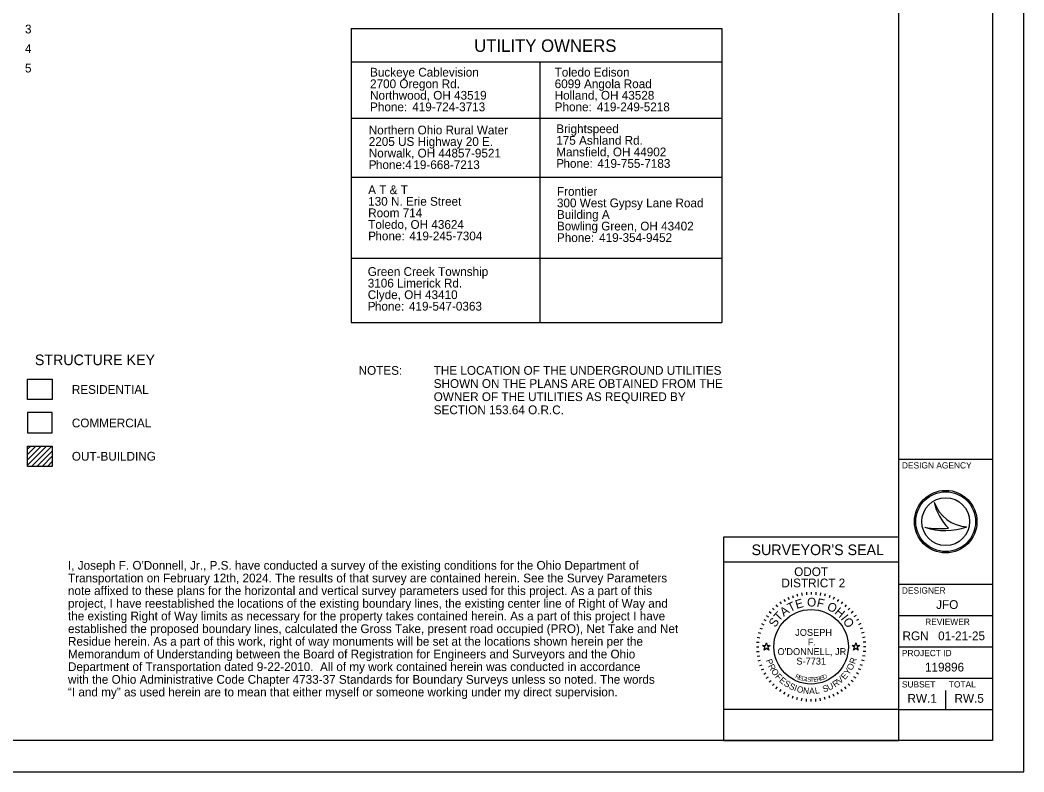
# Model space of a CAD drawing. Extents: x 0 to 34, y 0 to 22.
# Drawn here: x 17.96 to 34, y 0 to 12.02 of the extents above; entities that cross this region are included whole.
import ezdxf

# ---------------------------------------------------------------- set-up
doc = ezdxf.new("R2010")
doc.units = 0
for name, color, linetype in [('Default', 7, 'Continuous'), ('SC_Shading1', 7, 'Continuous'), ('SH_Border', 7, 'Continuous'), ('SH_Cut_Line', 7, 'Continuous'), ('SH_Data', 7, 'Continuous'), ('SH_Text', 7, 'Continuous')]:
    doc.layers.add(name, color=color, linetype=linetype)

msp = doc.modelspace()

# ---------------------------------------------------------------- linework, layer by layer
at = {"layer": 'Default'}
for points in [[(29.824, 2.02), (29.871, 2.02), (29.885, 2.065), (29.899, 2.02), (29.946, 2.02), (29.908, 1.992), (29.923, 1.948), (29.885, 1.975), (29.847, 1.948), (29.862, 1.992)], [(31.254, 2.02), (31.301, 2.02), (31.315, 2.065), (31.329, 2.02), (31.376, 2.02), (31.338, 1.992), (31.353, 1.948), (31.315, 1.975), (31.277, 1.948), (31.292, 1.992)]]:
    msp.add_lwpolyline(points, close=True, dxfattribs=at)
at = {"layer": 'SC_Shading1'}
msp.add_lwpolyline([(18.078, 5.417), (18.475, 5.417), (18.475, 5.743), (18.078, 5.743)], close=True, dxfattribs=at)
at = {"layer": 'SH_Border'}
for p, q in [((32, 0.5), (32, 21.5)), ((32, 5), (33.5, 5)), ((32, 3), (33.5, 3)), ((32, 2.5), (33.5, 2.5)), ((32, 2), (33.5, 2)), ((32, 1.5), (33.5, 1.5)), ((32, 1), (33.5, 1))]:
    msp.add_line(p, q, dxfattribs=at)
msp.add_lwpolyline([(1.5, 21.5), (33.5, 21.5), (33.5, 0.5), (1.5, 0.5)], close=True, dxfattribs=at)
at = {"layer": 'SH_Cut_Line'}
msp.add_lwpolyline([(0, 0), (34, 0), (34, 22), (0, 22)], close=True, dxfattribs=at)
at = {"layer": 'SH_Data'}
for p, q in [((32.567, 4.31), (32.567, 4.31)), ((32.417, 3.91), (32.417, 3.91)), ((32.75, 4), (32.75, 4)), ((33.087, 3.919), (33.087, 3.919)), ((32, 3.75), (29.2, 3.75)), ((29.2, 3.75), (29.2, 0.5)), ((32, 0.5), (32, 3.75)), ((32, 3.35), (29.2, 3.35)), ((30.163, 2.758), (30.183, 2.723)), ((30.23, 2.793), (30.247, 2.757)), ((30.301, 2.822), (30.314, 2.785)), ((30.374, 2.845), (30.384, 2.807)), ((30.448, 2.862), (30.455, 2.822)), ((30.524, 2.872), (30.527, 2.832)), ((30.6, 2.875), (30.6, 2.835)), ((30.676, 2.872), (30.673, 2.832)), ((30.752, 2.862), (30.745, 2.822)), ((30.826, 2.845), (30.816, 2.807)), ((30.899, 2.822), (30.886, 2.785)), ((30.97, 2.793), (30.953, 2.757)), ((31.037, 2.758), (31.017, 2.723)), ((29.981, 2.619), (30.01, 2.59)), ((30.038, 2.67), (30.063, 2.64)), ((30.098, 2.717), (30.121, 2.684)), ((31.102, 2.717), (31.079, 2.684)), ((31.162, 2.67), (31.137, 2.64)), ((31.219, 2.619), (31.19, 2.59)), ((29.842, 2.438), (29.877, 2.418)), ((29.883, 2.502), (29.916, 2.479)), ((29.93, 2.562), (29.96, 2.537)), ((31.27, 2.562), (31.24, 2.537)), ((31.317, 2.502), (31.284, 2.479)), ((31.358, 2.438), (31.323, 2.418)), ((29.778, 2.299), (29.815, 2.286)), ((29.807, 2.37), (29.843, 2.353)), ((31.393, 2.37), (31.357, 2.353)), ((31.422, 2.299), (31.385, 2.286)), ((29.738, 2.152), (29.778, 2.145)), ((29.755, 2.226), (29.793, 2.216)), ((31.445, 2.226), (31.407, 2.216)), ((31.462, 2.152), (31.422, 2.145)), ((29.725, 2), (29.765, 2)), ((29.728, 2.076), (29.768, 2.073)), ((29.728, 1.924), (29.768, 1.927)), ((31.472, 2.076), (31.432, 2.073)), ((31.472, 1.924), (31.432, 1.927)), ((31.475, 2), (31.435, 2)), ((29.738, 1.848), (29.778, 1.855)), ((29.755, 1.774), (29.793, 1.784)), ((31.445, 1.774), (31.407, 1.784)), ((31.462, 1.848), (31.422, 1.855)), ((29.778, 1.701), (29.815, 1.714)), ((29.807, 1.63), (29.843, 1.647)), ((31.393, 1.63), (31.357, 1.647)), ((31.422, 1.701), (31.385, 1.714)), ((29.842, 1.563), (29.877, 1.583)), ((29.883, 1.498), (29.916, 1.521)), ((29.93, 1.438), (29.96, 1.463)), ((31.27, 1.438), (31.24, 1.463)), ((31.317, 1.498), (31.284, 1.521)), ((31.358, 1.563), (31.323, 1.583)), ((29.981, 1.381), (30.01, 1.41)), ((30.038, 1.33), (30.063, 1.36)), ((30.098, 1.283), (30.121, 1.316)), ((31.102, 1.283), (31.079, 1.316)), ((31.162, 1.33), (31.137, 1.36)), ((31.219, 1.381), (31.19, 1.41)), ((32.75, 1), (32.75, 1.3)), ((30.163, 1.242), (30.183, 1.277)), ((30.23, 1.207), (30.247, 1.243)), ((30.301, 1.178), (30.314, 1.215)), ((30.374, 1.155), (30.384, 1.193)), ((30.448, 1.138), (30.455, 1.178)), ((30.524, 1.128), (30.527, 1.168)), ((30.6, 1.125), (30.6, 1.165)), ((30.676, 1.128), (30.673, 1.168)), ((30.752, 1.138), (30.745, 1.178)), ((30.826, 1.155), (30.816, 1.193)), ((30.899, 1.178), (30.886, 1.215)), ((30.97, 1.207), (30.953, 1.243)), ((31.037, 1.242), (31.017, 1.277)), ((32, 0.5), (29.2, 0.5))]:
    msp.add_line(p, q, dxfattribs=at)
msp.add_lwpolyline([(32, 0.5), (32, 1), (29.2, 1), (29.2, 0.5)], close=True, dxfattribs=at)
for centre, radius in [((32.75, 4), 0.5), ((32.75, 4), 0.477), ((32.75, 4), 0.477), ((32.75, 4), 0.382), ((30.6, 2), 0.595)]:
    msp.add_circle(centre, radius, dxfattribs=at)
for centre, radius, start, end in [((33.116, 4.498), 0.58, 198.9257, 198.9319), ((33.347, 4.47), 0.796, 191.6379, 191.6421), ((33.116, 4.498), 0.58, 198.9319, 267.1657), ((33.347, 4.47), 0.796, 191.6421, 226.0947), ((32.739, 4.87), 1.013, 251.4576, 290.0832), ((32.648, 5.154), 1.266, 259.4964, 259.4995), ((32.739, 4.87), 1.013, 251.4527, 251.4576), ((32.648, 5.154), 1.266, 259.4995, 276.6672)]:
    msp.add_arc(centre, radius, start, end, dxfattribs=at)
at = {"layer": 'SH_Text'}
for p, q in [((23.251, 11.882), (29.172, 11.882)), ((23.251, 11.882), (23.251, 7.184)), ((29.172, 11.882), (29.172, 7.184)), ((23.251, 11.351), (29.172, 11.351)), ((26.267, 11.351), (26.267, 7.184)), ((23.251, 10.449), (29.172, 10.449)), ((23.251, 9.505), (29.172, 9.505)), ((23.251, 8.212), (29.172, 8.212)), ((23.251, 7.184), (29.172, 7.184)), ((18.078, 5.206), (18.079, 5.207)), ((18.078, 5.156), (18.129, 5.207)), ((18.078, 5.071), (18.214, 5.207)), ((18.078, 4.986), (18.299, 5.207)), ((18.078, 4.902), (18.383, 5.207)), ((18.142, 4.881), (18.468, 5.207)), ((18.227, 4.881), (18.475, 5.129)), ((18.312, 4.881), (18.475, 5.045)), ((18.078, 4.886), (18.082, 4.881)), ((18.396, 4.881), (18.475, 4.96))]:
    msp.add_line(p, q, dxfattribs=at)
for points in [[(18.078, 6.278), (18.475, 6.278), (18.475, 5.952), (18.078, 5.952)], [(18.078, 5.207), (18.475, 5.207), (18.475, 4.881), (18.078, 4.881)]]:
    msp.add_lwpolyline(points, close=True, dxfattribs=at)

# ---------------------------------------------------------------- texts
at = {"layer": 'SH_Data'}
for s, height, p in [('3', 0.14, (18.038, 11.803)), ('4', 0.14, (18.038, 11.491)), ('5', 0.14, (18.038, 11.179)), ('DESIGN AGENCY', 0.1, (32.05, 4.85)), ("SURVEYOR'S SEAL", 0.17, (29.648, 3.465)), ('ODOT', 0.14, (30.329, 3.13)), ('DISTRICT 2', 0.14, (30.125, 2.95)), ('DESIGNER', 0.1, (32.05, 2.85)), ('JFO', 0.14, (32.598, 2.605)), ('REVIEWER', 0.1, (32.422, 2.35)), ('JOSEPH', 0.11, (30.345, 2.175)), ('RGN', 0.14, (32.06, 2.105)), ('01-21-25', 0.14, (32.629, 2.105)), ('F.', 0.11, (30.546, 2.022)), ("O'DONNELL, JR.", 0.11, (30.062, 1.868)), ('PROJECT ID', 0.1, (32.05, 1.85)), ('S-7731', 0.11, (30.364, 1.715)), ('119896', 0.14, (32.419, 1.605)), ('SUBSET', 0.1, (32.05, 1.35)), ('TOTAL', 0.1, (32.8, 1.35)), ('RW.1', 0.14, (32.14, 1.105)), ('RW.5', 0.14, (32.891, 1.105))]:
    msp.add_text(s, height=height, dxfattribs=at).set_placement(p)
for s, height, rotation, p in [('E', 0.14, 15.7571, (30.368, 2.604)), ('O', 0.14, 359.7812, (30.535, 2.644)), ('F', 0.14, 347.4362, (30.681, 2.642)), ('T', 0.14, 46.4344, (30.088, 2.396)), ('A', 0.14, 36.4747, (30.163, 2.478)), ('T', 0.14, 25.7167, (30.262, 2.552)), ('O', 0.14, 332.2586, (30.84, 2.602)), ('H', 0.14, 319.9136, (30.963, 2.536)), ('S', 0.14, 57.1924, (30.028, 2.301)), ('I', 0.14, 308.367, (31.066, 2.448)), ('O', 0.14, 303.1491, (31.102, 2.409)), ('P', 0.1, 289.7431, (29.875, 1.784)), ('R', 0.1, 70.983, (31.301, 1.717)), ('R', 0.1, 296.9802, (29.909, 1.693)), ('O', 0.1, 304.7158, (29.953, 1.608)), ('Y', 0.1, 55.5058, (31.2, 1.54)), ('O', 0.1, 62.7428, (31.25, 1.613)), ('F', 0.1, 312.956, (30.019, 1.516)), ('E', 0.1, 319.6885, (30.081, 1.45)), ('S', 0.1, 326.9255, (30.155, 1.389)), ('R', 0.07, 334.487, (30.337, 1.505)), ('E', 0.07, 341.04, (30.391, 1.48)), ('G', 0.07, 347.4752, (30.441, 1.462)), ('I', 0.07, 353.7858, (30.509, 1.447)), ('S', 0.07, 356.8926, (30.536, 1.443)), ('T', 0.07, 3.0061, (30.586, 1.439)), ('E', 0.07, 6.0117, (30.639, 1.441)), ('R', 0.07, 11.9184, (30.692, 1.447)), ('E', 0.07, 17.6836, (30.75, 1.46)), ('D', 0.07, 23.3052, (30.801, 1.477)), ('R', 0.1, 33.296, (30.981, 1.347)), ('V', 0.1, 41.0316, (31.061, 1.401)), ('E', 0.1, 48.2687, (31.137, 1.467)), ('S', 0.1, 334.1626, (30.236, 1.337)), ('I', 0.1, 341.3997, (30.319, 1.298)), ('O', 0.1, 345.1351, (30.362, 1.282)), ('N', 0.1, 353.3752, (30.466, 1.255)), ('A', 0.1, 1.1108, (30.569, 1.244)), ('L', 0.1, 8.3479, (30.666, 1.247)), ('S', 0.1, 18.3234, (30.8, 1.271)), ('U', 0.1, 25.5604, (30.883, 1.299))]:
    msp.add_text(s, height=height, rotation=rotation, dxfattribs=at).set_placement(p)
at = {"layer": 'SH_Text'}
for s, height, p in [('UTILITY OWNERS', 0.2, (25.215, 11.508)), ('Buckeye Cablevision', 0.14, (23.552, 11.113)), ('Toledo Edison', 0.14, (26.502, 11.113)), ('2700 Oregon Rd.', 0.14, (23.552, 10.928)), ('6099 Angola Road', 0.14, (26.502, 10.928)), ('Northwood, OH 43519 ', 0.14, (23.552, 10.744)), ('Holland, OH 43528 ', 0.14, (26.502, 10.744)), ('Phone: ', 0.14, (23.552, 10.559)), ('419-724-3713', 0.14, (24.226, 10.559)), ('Phone: ', 0.14, (26.502, 10.559)), ('419-249-5218', 0.14, (27.176, 10.559)), ('Northern Ohio Rural Water ', 0.14, (23.531, 10.189)), ('Brightspeed', 0.14, (26.527, 10.209)), ('2205 US Highway 20 E. ', 0.14, (23.531, 10.005)), ('175 Ashland Rd.', 0.14, (26.527, 10.024)), ('Norwalk, OH 44857-9521', 0.14, (23.531, 9.82)), ('Mansfield, OH 44902', 0.14, (26.527, 9.839)), ('P', 0.14, (26.527, 9.655)), ('hone: ', 0.14, (26.642, 9.655)), ('419-755-7183', 0.14, (27.185, 9.655)), ('P', 0.14, (23.531, 9.635)), ('hone:4', 0.14, (23.646, 9.635)), ('19-668-7213', 0.14, (24.244, 9.635)), ('A T & T', 0.14, (23.522, 9.234)), ('Frontier', 0.14, (26.538, 9.208)), ('130 N. Erie Street', 0.14, (23.522, 9.049)), ('300 West Gypsy Lane Road', 0.14, (26.538, 9.024)), ('Room 714', 0.14, (23.522, 8.865)), ('Building A ', 0.14, (26.538, 8.839)), ('Toledo, OH 43624 ', 0.14, (23.522, 8.68)), ('Bowling Green, OH 43402', 0.14, (26.538, 8.654)), ('P', 0.14, (23.522, 8.496)), ('hone: ', 0.14, (23.637, 8.496)), ('419-245-7304', 0.14, (24.18, 8.496)), ('Phone: ', 0.14, (26.538, 8.47)), ('419-354-9452', 0.14, (27.212, 8.47)), ('Green Creek Township', 0.14, (23.515, 7.927)), ('3106 Limerick Rd.', 0.14, (23.515, 7.742)), ('Clyde, OH 43410', 0.14, (23.515, 7.557)), ('P', 0.14, (23.515, 7.373)), ('hone: ', 0.14, (23.63, 7.373)), ('419-547-0363', 0.14, (24.174, 7.373)), ('STRUCTURE KEY', 0.17, (18.196, 6.501)), ('NOTES:', 0.14, (23.369, 6.347)), ('THE LOCATION OF THE UNDERGROUND UTILITIES', 0.14, (24.569, 6.347)), ('SHOWN ON THE PLANS ARE OBTAINED FROM THE', 0.14, (24.569, 6.137)), ('RESIDENTIAL', 0.14, (18.787, 6.042)), ('OWNER OF THE UTILITIES AS REQUIRED BY', 0.14, (24.569, 5.927)), ('SECTION 153.64 O.R.C.', 0.14, (24.569, 5.717)), ('COMMERCIAL', 0.14, (18.787, 5.507)), ('OUT-BUILDING', 0.14, (18.787, 4.975)), ("I, Joseph F. O'Donnell, Jr., P.S. have conducted a survey of the existing conditions for the Ohio Department of ", 0.14, (18.725, 3.232)), ('Transportation on February 12th, 2024. The results of that survey are contained herein. See the Survey Parameters', 0.14, (18.725, 3.029)), ('note affixed to these plans for the horizontal and vertical survey parameters used for this project. As a part of this', 0.14, (18.725, 2.827)), ('project, I have reestablished the locations of the existing boundary lines, the existing center line of Right of Way and', 0.14, (18.725, 2.624)), ('the existing Right of Way limits as necessary for the property takes contained herein. As a part of this project I have', 0.14, (18.725, 2.422)), ('established the proposed boundary lines, calculated the Gross Take, present road occupied (PRO), Net Take and Net', 0.14, (18.725, 2.219)), ('Residue herein. As a part of this work, right of way monuments will be set at the locations shown herein per the ', 0.14, (18.725, 2.017)), ('Memorandum of Understanding between the Board of Registration for Engineers and Surveyors and the Ohio ', 0.14, (18.725, 1.814)), ('Department of Transportation dated 9-22-2010.  All of my work contained herein was conducted in accordance ', 0.14, (18.725, 1.612)), ('with the Ohio Administrative Code Chapter 4733-37 Standards for Boundary Surveys unless so noted. The words ', 0.14, (18.725, 1.409)), ('“I and my” as used herein are to mean that either myself or someone working under my direct supervision.', 0.14, (18.725, 1.207))]:
    msp.add_text(s, height=height, dxfattribs=at).set_placement(p)

doc.saveas('drawing.dxf')
